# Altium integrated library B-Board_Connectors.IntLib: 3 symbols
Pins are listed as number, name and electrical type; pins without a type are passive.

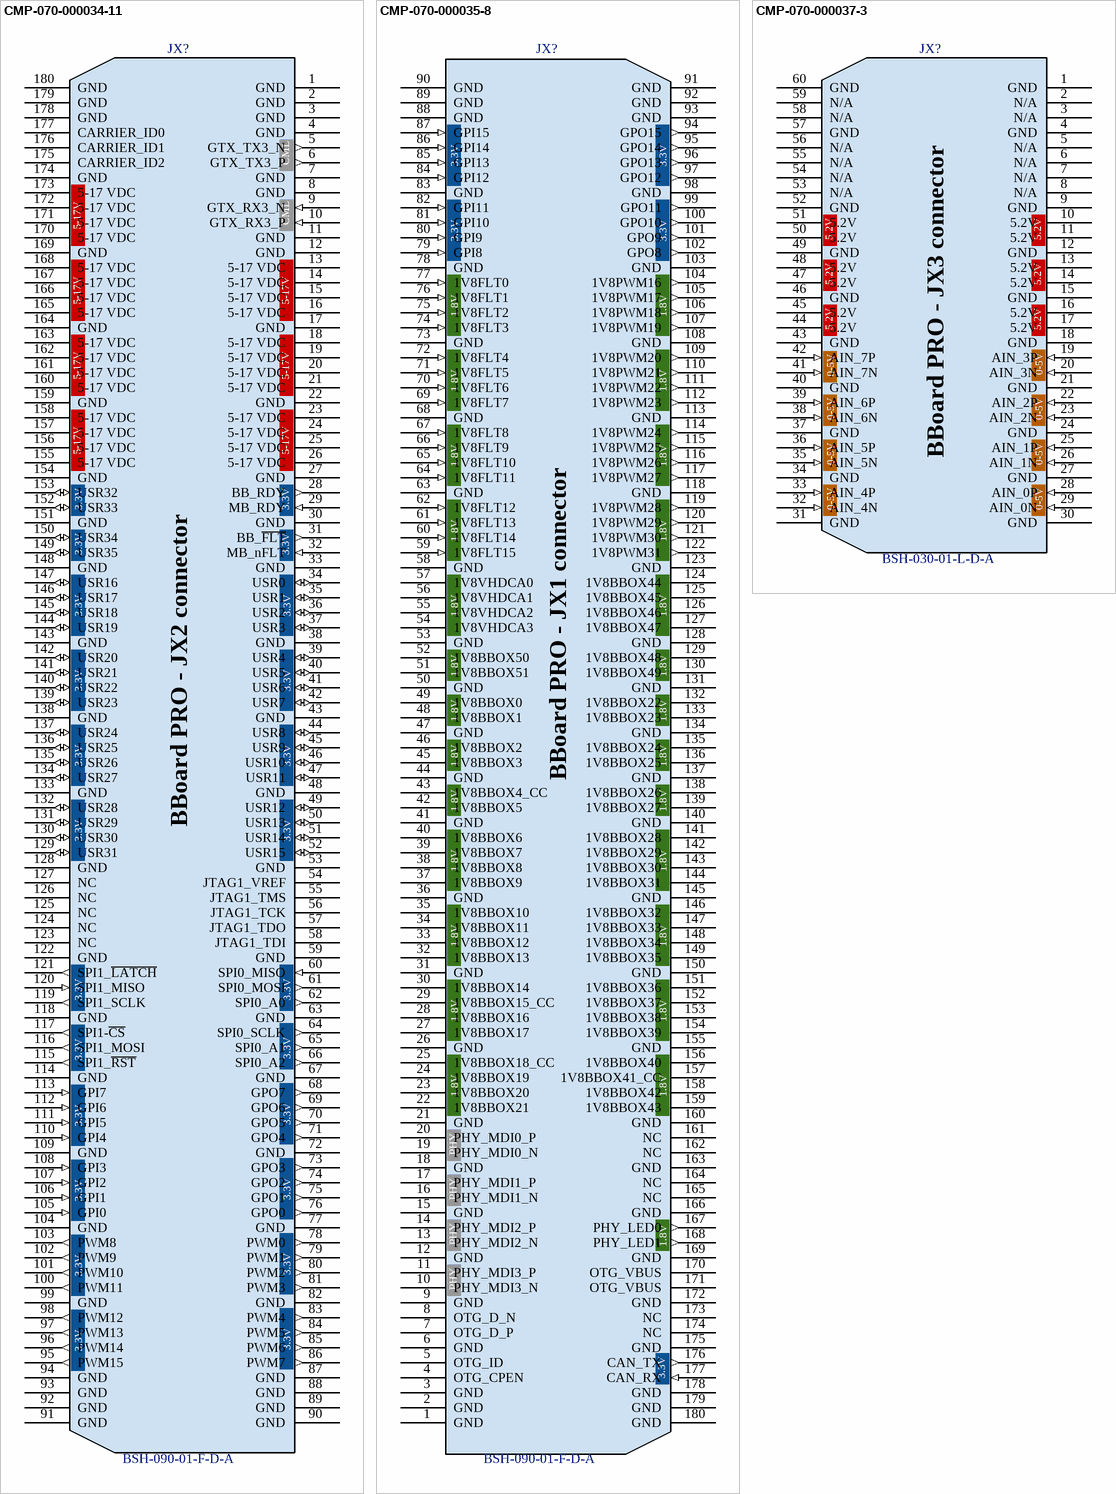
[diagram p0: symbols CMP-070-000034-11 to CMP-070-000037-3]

## CMP-070-000034-11
designator JX?, comment BSH-090-01-F-D-A
JX2 for BBoard; Manufacturer: Samtec; Number of Contacts: 180; Gender: Female; Pitch: 0.5mm; Mated Stacking Heights: 5mm; Max Current Rating: 1.25A; Max Voltage Rating (AC): 125V
footprint BSH-090-01-F-D-A (Conn Micro Socket SKT 180 POS 0.5mm Solder ST SMD Automotive Tray)
pins: 1 GND (power), 2 GND (power), 3 GND (power), 4 GND (power), 5 GTX_TX3_N (out), 6 GTX_TX3_P (out), 7 GND (power), 8 GND (power), 9 GTX_RX3_N (in), 10 GTX_RX3_P (in), 11 GND (power), 12 GND (power), 13 5-17 VDC (power), 14 5-17 VDC (power), 15 5-17 VDC (power), 16 5-17 VDC (power), 17 GND (power), 18 5-17 VDC (power), 19 5-17 VDC (power), 20 5-17 VDC (power), 21 5-17 VDC (power), 22 GND (power), 23 5-17 VDC (power), 24 5-17 VDC (power), 25 5-17 VDC (power), 26 5-17 VDC (power), 27 GND (power), 28 BB_RDY (out), 29 MB_RDY (in), 30 GND (power), 31 BB_~{FLT} (out), 32 MB_nFLT (in), 33 GND (power), 34 USR0 (io), 35 USR1 (io), 36 USR2 (io), 37 USR3 (io), 38 GND (power), 39 USR4 (io), 40 USR5 (io), 41 USR6 (io), 42 USR7 (io), 43 GND (power), 44 USR8 (io), 45 USR9 (io), 46 USR10 (io), 47 USR11 (io), 48 GND (power), 49 USR12 (io), 50 USR13 (io), 51 USR14 (io), 52 USR15 (io), 53 GND (power), 54 JTAG1_VREF, 55 JTAG1_TMS, 56 JTAG1_TCK, 57 JTAG1_TDO, 58 JTAG1_TDI, 59 GND (power), 60 SPI0_MISO (in), 61 SPI0_MOSI (out), 62 SPI0_A0 (out), 63 GND (power), 64 SPI0_SCLK (out), 65 SPI0_A1 (out), 66 SPI0_A2 (out), 67 GND (power), 68 GPO7 (out), 69 GPO6 (out), 70 GPO5 (out), 71 GPO4 (out), 72 GND (power), 73 GPO3 (out), 74 GPO2 (out), 75 GPO1 (out), 76 GPO0 (out), 77 GND (power), 78 PWM0 (out), 79 PWM1 (out), 80 PWM2 (out), 81 PWM3 (out), 82 GND (power), 83 PWM4 (out), 84 PWM5 (out), 85 PWM6 (out), 86 PWM7 (out), 87 GND (power), 88 GND (power), 89 GND (power), 90 GND (power), 91 GND (power), 92 GND (power), 93 GND (power), 94 GND (power), 95 PWM15 (out), 96 PWM14 (out), 97 PWM13 (out), 98 PWM12 (out), 99 GND (power), 100 PWM11 (out), 101 PWM10 (out), 102 PWM9 (out), 103 PWM8 (out), 104 GND (power), 105 GPI0 (in), 106 GPI1 (in), 107 GPI2 (in), 108 GPI3 (in), 109 GND (power), 110 GPI4 (in), 111 GPI5 (in), 112 GPI6 (in), 113 GPI7 (in), 114 GND (power), 115 SPI1_~{RST} (out), 116 SPI1_MOSI (out), 117 SPI1-~{CS} (out), 118 GND (power), 119 SPI1_SCLK (out), 120 SPI1_MISO (in), 121 SPI1_~{LATCH} (out), 122 GND (power), 123 NC, 124 NC, 125 NC, 126 NC, 127 NC, 128 GND (power), 129 USR31 (io), 130 USR30 (io), 131 USR29 (io), 132 USR28 (io), 133 GND (power), 134 USR27 (io), 135 USR26 (io), 136 USR25 (io), 137 USR24 (io), 138 GND (power), 139 USR23 (io), 140 USR22 (io), 141 USR21 (io), 142 USR20 (io), 143 GND (power), 144 USR19 (io), 145 USR18 (io), 146 USR17 (io), 147 USR16 (io), 148 GND (power), 149 USR35 (io), 150 USR34 (io), 151 GND (power), 152 USR33 (io), 153 USR32 (io), 154 GND (power), 155 5-17 VDC (power), 156 5-17 VDC (power), 157 5-17 VDC (power), 158 5-17 VDC (power), 159 GND (power), 160 5-17 VDC (power), 161 5-17 VDC (power), 162 5-17 VDC (power), 163 5-17 VDC (power), 164 GND (power), 165 5-17 VDC (power), 166 5-17 VDC (power), 167 5-17 VDC (power), 168 5-17 VDC (power), 169 GND (power), 170 5-17 VDC (power), 171 5-17 VDC (power), 172 5-17 VDC (power), 173 5-17 VDC (power), 174 GND (power), 175 CARRIER_ID2, 176 CARRIER_ID1, 177 CARRIER_ID0, 178 GND (power), 179 GND (power), 180 GND (power)

## CMP-070-000035-8
designator JX?, comment BSH-090-01-F-D-A
JX1 for BBoard; Manufacturer: Samtec; Max Current Rating: 1.25A; Number of Contacts: 180; Pitch: 0.5mm; Mated Stacking Heights: 5mm; Gender: Female; Max Voltage Rating (AC): 125V
footprint BSH-090-01-F-D-A (Conn Micro Socket SKT 180 POS 0.5mm Solder ST SMD Automotive Tray)
pins: 1 GND (power), 2 GND (power), 3 GND (power), 4 OTG_CPEN, 5 OTG_ID, 6 GND (power), 7 OTG_D_P, 8 OTG_D_N, 9 GND (power), 10 PHY_MDI3_N, 11 PHY_MDI3_P, 12 GND (power), 13 PHY_MDI2_N, 14 PHY_MDI2_P, 15 GND (power), 16 PHY_MDI1_N, 17 PHY_MDI1_P, 18 GND (power), 19 PHY_MDI0_N, 20 PHY_MDI0_P, 21 GND (power), 22 1V8BBOX21, 23 1V8BBOX20, 24 1V8BBOX19, 25 1V8BBOX18_CC, 26 GND (power), 27 1V8BBOX17, 28 1V8BBOX16, 29 1V8BBOX15_CC, 30 1V8BBOX14, 31 GND (power), 32 1V8BBOX13, 33 1V8BBOX12, 34 1V8BBOX11, 35 1V8BBOX10, 36 GND (power), 37 1V8BBOX9, 38 1V8BBOX8, 39 1V8BBOX7, 40 1V8BBOX6, 41 GND (power), 42 1V8BBOX5, 43 1V8BBOX4_CC, 44 GND (power), 45 1V8BBOX3, 46 1V8BBOX2, 47 GND (power), 48 1V8BBOX1, 49 1V8BBOX0, 50 GND (power), 51 1V8BBOX51, 52 1V8BBOX50, 53 GND (power), 54 1V8VHDCA3, 55 1V8VHDCA2, 56 1V8VHDCA1, 57 1V8VHDCA0, 58 GND (power), 59 1V8FLT15 (in), 60 1V8FLT14 (in), 61 1V8FLT13 (in), 62 1V8FLT12 (in), 63 GND (power), 64 1V8FLT11 (in), 65 1V8FLT10 (in), 66 1V8FLT9 (in), 67 1V8FLT8 (in), 68 GND (power), 69 1V8FLT7 (in), 70 1V8FLT6 (in), 71 1V8FLT5 (in), 72 1V8FLT4 (in), 73 GND (power), 74 1V8FLT3 (in), 75 1V8FLT2 (in), 76 1V8FLT1 (in), 77 1V8FLT0 (in), 78 GND (power), 79 GPI8 (in), 80 GPI9 (in), 81 GPI10 (in), 82 GPI11 (in), 83 GND (power), 84 GPI12 (in), 85 GPI13 (in), 86 GPI14 (in), 87 GPI15 (in), 88 GND (power), 89 GND (power), 90 GND (power), 91 GND (power), 92 GND (power), 93 GND (power), 94 GPO15 (out), 95 GPO14 (out), 96 GPO13 (out), 97 GPO12 (out), 98 GND (power), 99 GPO11 (out), 100 GPO10 (out), 101 GPO9 (out), 102 GPO8 (out), 103 GND (power), 104 1V8PWM16 (out), 105 1V8PWM17 (out), 106 1V8PWM18 (out), 107 1V8PWM19 (out), 108 GND (power), 109 1V8PWM20 (out), 110 1V8PWM21 (out), 111 1V8PWM22 (out), 112 1V8PWM23 (out), 113 GND (power), 114 1V8PWM24 (out), 115 1V8PWM25 (out), 116 1V8PWM26 (out), 117 1V8PWM27 (out), 118 GND (power), 119 1V8PWM28 (out), 120 1V8PWM29 (out), 121 1V8PWM30 (out), 122 1V8PWM31 (out), 123 GND (power), 124 1V8BBOX44, 125 1V8BBOX45, 126 1V8BBOX46, 127 1V8BBOX47, 128 GND (power), 129 1V8BBOX48, 130 1V8BBOX49, 131 GND (power), 132 1V8BBOX22, 133 1V8BBOX23, 134 GND (power), 135 1V8BBOX24, 136 1V8BBOX25, 137 GND (power), 138 1V8BBOX26, 139 1V8BBOX27, 140 GND (power), 141 1V8BBOX28, 142 1V8BBOX29, 143 1V8BBOX30, 144 1V8BBOX31, 145 GND (power), 146 1V8BBOX32, 147 1V8BBOX33, 148 1V8BBOX34, 149 1V8BBOX35, 150 GND (power), 151 1V8BBOX36, 152 1V8BBOX37, 153 1V8BBOX38, 154 1V8BBOX39, 155 GND (power), 156 1V8BBOX40, 157 1V8BBOX41_CC, 158 1V8BBOX42, 159 1V8BBOX43, 160 GND (power), 161 NC, 162 NC, 163 GND (power), 164 NC, 165 NC, 166 GND (power), 167 PHY_LED0 (out), 168 PHY_LED1 (out), 169 GND (power), 170 OTG_VBUS, 171 OTG_VBUS, 172 GND (power), 173 NC, 174 NC, 175 GND (power), 176 CAN_TX (out), 177 CAN_RX (in), 178 GND (power), 179 GND (power), 180 GND (power)

## CMP-070-000037-3
designator JX?, comment BSH-030-01-L-D-A
JX3 for BBoard; Manufacturer: Samtec; Mated Stacking Heights: 5mm; Gender: Female; Number of Positions: 60; Pitch: 0.5mm
footprint BSH-030-01-L-D-A (Conn Micro Socket SKT 60 POS 0.5mm Solder ST SMD Automotive Tray)
pins: 1 GND (power), 2 N/A, 3 N/A, 4 GND (power), 5 N/A, 6 N/A, 7 N/A, 8 N/A, 9 GND (power), 10 5.2V (power), 11 5.2V (power), 12 GND (power), 13 5.2V (power), 14 5.2V (power), 15 GND (power), 16 5.2V (power), 17 5.2V (power), 18 GND (power), 19 AIN_3P (in), 20 AIN_3N (in), 21 GND (power), 22 AIN_2P (in), 23 AIN_2N (in), 24 GND (power), 25 AIN_1P (in), 26 AIN_1N (in), 27 GND (power), 28 AIN_0P (in), 29 AIN_0N (in), 30 GND (power), 31 GND (power), 32 AIN_4N (in), 33 AIN_4P (in), 34 GND (power), 35 AIN_5N (in), 36 AIN_5P (in), 37 GND (power), 38 AIN_6N (in), 39 AIN_6P (in), 40 GND (power), 41 AIN_7N (in), 42 AIN_7P (in), 43 GND (power), 44 5.2V (power), 45 5.2V (power), 46 GND (power), 47 5.2V (power), 48 5.2V (power), 49 GND (power), 50 5.2V (power), 51 5.2V (power), 52 GND (power), 53 N/A, 54 N/A, 55 N/A, 56 N/A, 57 GND (power), 58 N/A, 59 N/A, 60 GND (power)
